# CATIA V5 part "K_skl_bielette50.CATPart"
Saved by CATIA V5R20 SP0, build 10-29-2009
Part number: skl_biellette 50
Publications: "longueur axe pivot", "liaison 57/50", "liaison 51/50", "Plan.-30", "Droite.1", "Droite.2", "Droite.3"
Bounding box of the stored display mesh (mm): x -30 to 120, y -660 to -545, z 765 to 795
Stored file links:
  G:\Khaled_CFAO_2011\SIL\SIL_GR2\mdardier\Khaled\CAD_ThinkMOTION\K_skl_bielette50.CATPart
  G:\Khaled_CFAO_2011\SIL\SIL_GR2\mdardier\Khaled\CAD_ThinkMOTION\K_skl_ass_tandem.CATProduct
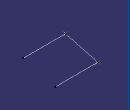
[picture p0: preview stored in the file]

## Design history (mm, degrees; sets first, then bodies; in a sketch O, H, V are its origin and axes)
External parameters (linked from other documents)
  `External.longueur axe pivot` = 150 mm
Set1
  Point1 "liaison 57/50": linked copy from another document
  Point2 "liaison 51/50": linked copy from another document
  Plane1 "Plan.-30": linked copy from another document
Set2
  Line1: type PtPt, FirstPoint Point1, SecondPoint Point2
  Line2: type Normal, RefPoint Point1, RefSkin Plane1, Start 0, End 150 {= `External.longueur axe pivot`}
  Line3: type Normal, RefPoint Point2, RefSkin Plane1, Start 0, End 150 {= `External.longueur axe pivot`}
Body1 (main body)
